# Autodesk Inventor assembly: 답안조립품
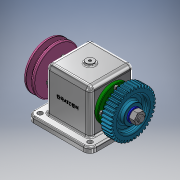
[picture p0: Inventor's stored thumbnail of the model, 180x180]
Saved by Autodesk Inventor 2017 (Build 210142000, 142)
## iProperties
Part Number: 답안조립품
Material: 일반
Document SubType Name: Assembly
Designer: MRC
Author: MRC
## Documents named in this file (12)
- C:\Users\MRC\Desktop\720706V1016\답안조립품.iam
- C:\Users\MRC\Desktop\720706V1016\V벨트풀리.ipt
- C:\Users\MRC\Desktop\720706V1016\너트 M12x1.25.ipt
- C:\Users\MRC\Desktop\720706V1016\베어링 6204.ipt
- C:\Users\MRC\Desktop\720706V1016\본체.ipt
- C:\Users\MRC\Desktop\720706V1016\볼트 M4x0.7.ipt
- C:\Users\MRC\Desktop\720706V1016\스퍼기어.ipt
- C:\Users\MRC\Desktop\720706V1016\오일실 20x35x8.ipt
- C:\Users\MRC\Desktop\720706V1016\와셔 12x24.ipt
- C:\Users\MRC\Desktop\720706V1016\축.ipt
- C:\Users\MRC\Desktop\720706V1016\커버.ipt
- C:\Users\MRC\Desktop\720706V1016\키 5x5.ipt
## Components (1 placed, 1 different names)
1. V벨트풀리:1
